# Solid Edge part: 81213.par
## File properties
Title: cylindrical roller thrust bearing 81213
Author: TraceParts S.A.
Template: Iso Metric Part.par
Last saved by: Nimesh.N
Revision: 11
Application: TraceParts
Company: TraceParts S.A.
Accuracy: 0.990
REFERENCE: 81213
SUPPLIER: STC-STEYR Wälzlager Deutschland GmbH
DESIGN: cylindrical roller thrust bearing 81213
TraceParts.PartNumber: 90-17062021-065719
TraceParts.PartTitle: cylindrical roller thrust bearing
TraceParts.InstanceId: 90-17062021-06571942R82R7EIMCNB8PN8MVQ48BQC
TRACEPARTS: TRACEPARTS
TraceParts.PartLanguage: en
TraceParts.PartVersion: 1.0.5
Username: Nimesh.N
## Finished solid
Body 1: solid body, 3 faces, 2 edges, 2 vertices.
  Faces by surface: plane 2, cylinder 1
  Edges by curve: circle 2
Body 2: solid body, 7 faces, 7 edges, 7 vertices.
  Faces by surface: cone 2, cylinder 2, plane 2, torus 1
  Edges by curve: circle 7
Body 3: solid body, 3 faces, 2 edges, 2 vertices.
  Faces by surface: plane 2, cylinder 1
  Edges by curve: circle 2
Body 4: solid body, 3 faces, 2 edges, 2 vertices.
  Faces by surface: plane 2, cylinder 1
  Edges by curve: circle 2
Body 5: solid body, 3 faces, 2 edges, 2 vertices.
  Faces by surface: plane 2, cylinder 1
  Edges by curve: circle 2
Body 6: solid body, 3 faces, 2 edges, 2 vertices.
  Faces by surface: plane 2, cylinder 1
  Edges by curve: circle 2
Body 7: solid body, 3 faces, 2 edges, 2 vertices.
  Faces by surface: plane 2, cylinder 1
  Edges by curve: circle 2
Body 8: solid body, 3 faces, 2 edges, 2 vertices.
  Faces by surface: plane 2, cylinder 1
  Edges by curve: circle 2
Body 9: solid body, 3 faces, 2 edges, 2 vertices.
  Faces by surface: plane 2, cylinder 1
  Edges by curve: circle 2
Body 10: solid body, 3 faces, 2 edges, 2 vertices.
  Faces by surface: plane 2, cylinder 1
  Edges by curve: circle 2
Body 11: solid body, 3 faces, 2 edges, 2 vertices.
  Faces by surface: plane 2, cylinder 1
  Edges by curve: circle 2
Body 12: solid body, 3 faces, 2 edges, 2 vertices.
  Faces by surface: plane 2, cylinder 1
  Edges by curve: circle 2
Body 13: solid body, 3 faces, 2 edges, 2 vertices.
  Faces by surface: plane 2, cylinder 1
  Edges by curve: circle 2
Body 14: solid body, 3 faces, 2 edges, 2 vertices.
  Faces by surface: plane 2, cylinder 1
  Edges by curve: circle 2
Body 15: solid body, 3 faces, 2 edges, 2 vertices.
  Faces by surface: plane 2, cylinder 1
  Edges by curve: circle 2
Body 16: solid body, 3 faces, 2 edges, 2 vertices.
  Faces by surface: plane 2, cylinder 1
  Edges by curve: circle 2
Body 17: solid body, 3 faces, 2 edges, 2 vertices.
  Faces by surface: plane 2, cylinder 1
  Edges by curve: circle 2
Body 18: solid body, 7 faces, 7 edges, 7 vertices.
  Faces by surface: cone 2, cylinder 2, plane 2, torus 1
  Edges by curve: circle 7
Bounding box of the edges (mm; curved faces can reach further): 100.000 x 27.000 x 100.000, from (-50, 0, -50) to (50, 27, 50).
Cylindrical faces by radius (mm): R4.5 x16, R32.5 x1, R33.85 x1, R48.65 x1, R50 x1
Conical faces (half-angle, radius in mm at the cone's reference point): 45 deg R33.175 x1, 45 deg R34.525 x1, 45 deg R47.975 x1, 45 deg R49.325 x1
Toroidal faces (ring radius, tube radius in mm): R47.975 r0.675 x1, R49.325 r0.675 x1
Planar faces by outward normal: +x 2, +y 2, +z 2, -x 2, -y 2, -z 2, oblique 24
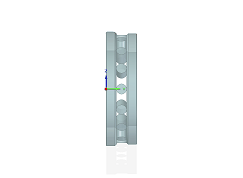
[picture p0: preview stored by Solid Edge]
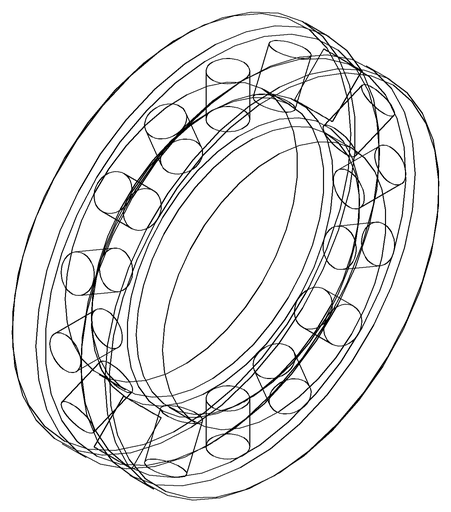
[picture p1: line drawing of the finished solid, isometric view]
